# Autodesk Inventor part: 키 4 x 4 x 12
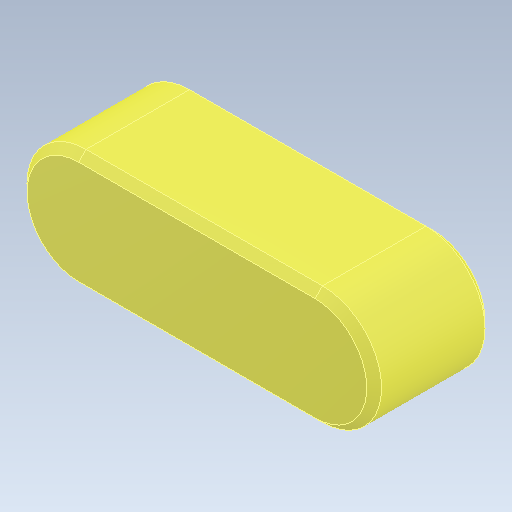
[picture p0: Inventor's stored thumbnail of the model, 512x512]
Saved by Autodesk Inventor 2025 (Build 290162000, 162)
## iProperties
Created: 2024-07
Part Number: 키 4 x 4 x 12
Material: 강철, 연강
Description: 키 및 해당 키홈
Document SubType Name: Modeling
Designer: 미서니
Density: 7.85 g/cm^3
Appearance: 기본값
Author: jhkim
Sending System: Autodesk Inventor 2025
Preprocessor: ST-DEVELOPER v20
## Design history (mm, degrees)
feature "Solid1"
node "솔리드1"
